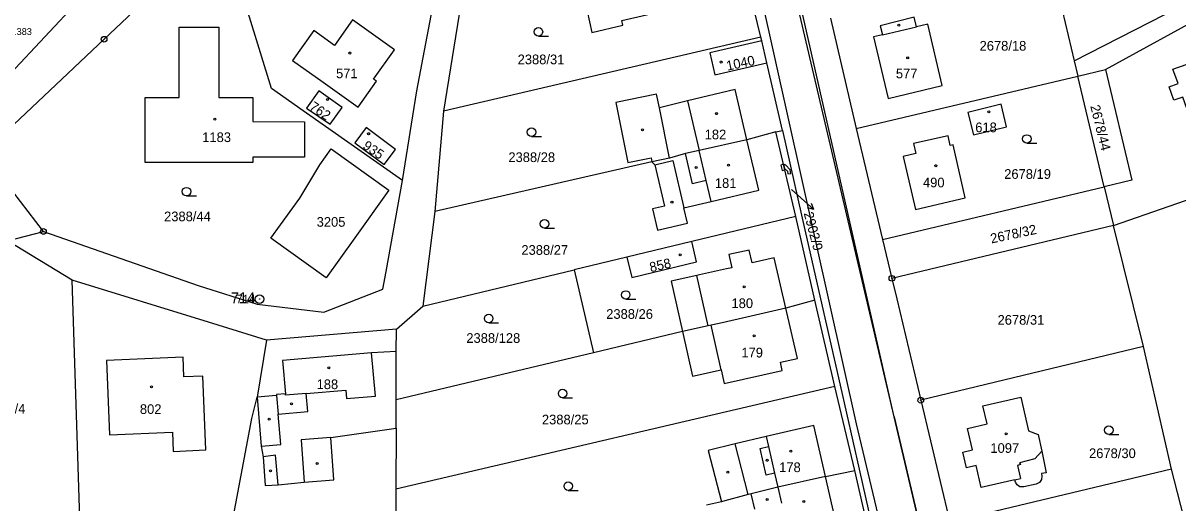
# Model space of a CAD drawing. Extents: x -758836 to -757729, y -1175316 to -1174366.
# Drawn here: x -758487.7 to -758284.7, y -1175013.2 to -1174928.9 of the extents above; entities that cross this region are included whole.
import ezdxf

# ---------------------------------------------------------------- set-up
doc = ezdxf.new("R2010")
doc.units = 0
for name, color, linetype in [('Hranice parcel', 7, 'Continuous'), ('Parcelní čísla', 7, 'Continuous'), ('Pop  PČ popisy', 7, 'Continuous'), ('Vnitřní kresba', 7, 'Continuous'), ('Vrstva 61', 7, 'Continuous'), ('Věcná břemena k části', 7, 'Continuous'), ('Značky bodu BP', 7, 'Continuous'), ('Značky budov', 7, 'Continuous'), ('Značky kultur', 7, 'Continuous')]:
    doc.layers.add(name, color=color, linetype=linetype)

msp = doc.modelspace()

# ---------------------------------------------------------------- linework, layer by layer
at = {"layer": 'Hranice parcel'}
for p, q in [((-758357.99, -1174931.4), (-758362.06, -1174914.46)), ((-758306.92, -1174918.8), (-758302.92, -1174935.57)), ((-758345.78, -1174928.06), (-758341.26, -1174947.41)), ((-758357.99, -1174931.4), (-758413.76, -1174944.36)), ((-758357.84, -1174932.05), (-758357.99, -1174931.4)), ((-758356.95, -1174935.89), (-758357.84, -1174932.05)), ((-758354.19, -1174947.79), (-758356.95, -1174935.89)), ((-758302.92, -1174935.57), (-758302.28, -1174938.23)), ((-758302.28, -1174938.23), (-758297.41, -1174937.08)), ((-758341.26, -1174947.41), (-758302.28, -1174938.23)), ((-758413.76, -1174944.36), (-758415.31, -1174962.01)), ((-758355.36, -1174948.01), (-758360.44, -1174949.43)), ((-758355.36, -1174948.01), (-758354.19, -1174947.79)), ((-758351.86, -1174962.91), (-758355.36, -1174948.01)), ((-758341.26, -1174947.41), (-758336.59, -1174966.93)), ((-758484.1, -1174965.51), (-758494.7, -1174951.75)), ((-758377.14, -1174953.27), (-758415.31, -1174962.01)), ((-758336.59, -1174966.93), (-758297.64, -1174957.65)), ((-758297.64, -1174957.65), (-758296.01, -1174964.46)), ((-758415.31, -1174962.01), (-758417.43, -1174978.6)), ((-758351.86, -1174962.91), (-758370.14, -1174967.28)), ((-758348.51, -1174977.6), (-758351.86, -1174962.91)), ((-758490.43, -1174967.13), (-758484.1, -1174965.51)), ((-758296.01, -1174964.46), (-758334.97, -1174973.74)), ((-758290.72, -1174985.7), (-758296.01, -1174964.46)), ((-758479.07, -1174974.04), (-758490.43, -1174967.13)), ((-758370.14, -1174967.28), (-758381.55, -1174970.01)), ((-758336.59, -1174966.93), (-758334.97, -1174973.74)), ((-758360.06, -1174968.77), (-758363.6, -1174969.56)), ((-758381.55, -1174970.01), (-758390.82, -1174972.23)), ((-758417.43, -1174978.6), (-758390.82, -1174972.23)), ((-758390.82, -1174972.23), (-758387.4, -1174986.81)), ((-758477.28, -1175030), (-758479.07, -1174974.04)), ((-758348.51, -1174977.6), (-758353.61, -1174978.97)), ((-758345.02, -1174992.7), (-758348.51, -1174977.6)), ((-758422.04, -1174982.66), (-758417.43, -1174978.6)), ((-758422.04, -1174982.66), (-758444.91, -1174984.58)), ((-758371.77, -1174983.1), (-758387.4, -1174986.81)), ((-758444.91, -1174984.58), (-758446.54, -1174994.59)), ((-758290.72, -1174985.7), (-758329.89, -1174995.14)), ((-758285.8, -1175007.25), (-758290.72, -1174985.7)), ((-758387.4, -1174986.81), (-758422.1, -1174995.06)), ((-758345.02, -1174992.7), (-758422.18, -1175010.77)), ((-758341.49, -1175007.47), (-758345.02, -1174992.7)), ((-758422.13, -1175000.03), (-758422.1, -1174995.06)), ((-758329.89, -1174995.14), (-758324.8, -1175016.55)), ((-758422.13, -1175000.03), (-758422.18, -1175010.77)), ((-758346.66, -1175008.52), (-758341.49, -1175007.47)), ((-758338.16, -1175021.98), (-758341.49, -1175007.47)), ((-758285.8, -1175007.25), (-758324.8, -1175016.55)), ((-758280.48, -1175027.85), (-758285.8, -1175007.25)), ((-758422.18, -1175010.77), (-758422.16, -1175026.87)), ((-758364.93, -1175012.95), (-758367.53, -1175013.58))]:
    msp.add_line(p, q, dxfattribs=at)
for points in [[(-758297.14, -1175157.07), (-758301.82, -1175137.17), (-758334.58, -1174998.03), (-758360.35, -1174888.27), (-758361.81, -1174882.07)], [(-758302.92, -1174935.57), (-758286.99, -1174927.44), (-758267.9, -1174916.47), (-758249.14, -1174905.98), (-758236.24, -1174897.16), (-758223.14, -1174884.37)], [(-758420.99, -1174956.58), (-758418.47, -1174940.81), (-758410.71, -1174900.14)], [(-758544.35, -1174980.07), (-758534.26, -1174973.76), (-758489.89, -1174937.8), (-758465.75, -1174911.99), (-758459.45, -1174912.25)], [(-758456.16, -1174915.41), (-758473.44, -1174931.75), (-758494.7, -1174951.75)], [(-758386.48, -1174920.18), (-758385.14, -1174926.03), (-758388.55, -1174926.82), (-758387.71, -1174930.55), (-758382.23, -1174929.27), (-758382.42, -1174928.48), (-758374.55, -1174926.68), (-758366.2, -1174924.79), (-758368.18, -1174916.07)], [(-758297.41, -1174937.08), (-758278.62, -1174926.8), (-758276.96, -1174925.54), (-758269.21, -1174920.77)], [(-758296.01, -1174964.46), (-758247.07, -1174947.51), (-758269.21, -1174920.77)], [(-758410.64, -1174925.24), (-758410.72, -1174925.53), (-758413.76, -1174944.36)], [(-758420.99, -1174956.58), (-758438.47, -1174944.3), (-758444.03, -1174940.39), (-758448.12, -1174927.13)], [(-758422.41, -1174933.59), (-758429.78, -1174928.35), (-758432.94, -1174932.84), (-758436.6, -1174930.22), (-758440.31, -1174935.48), (-758434.92, -1174939.3), (-758428.76, -1174943.67), (-758425.55, -1174939.12), (-758426.06, -1174938.77), (-758422.41, -1174933.59)], [(-758326.1, -1174939.86), (-758328.65, -1174929.09), (-758330.65, -1174929.56), (-758331.04, -1174927.9), (-758337.01, -1174929.38), (-758336.63, -1174930.98), (-758338.22, -1174931.36), (-758335.63, -1174942.14), (-758326.1, -1174939.86)], [(-758460.27, -1174942), (-758460.27, -1174929.65), (-758453.25, -1174929.64), (-758453.27, -1174941.98), (-758447.28, -1174941.99), (-758447.29, -1174946.22), (-758438.2, -1174946.25), (-758438.23, -1174952.48), (-758447.31, -1174952.45), (-758447.31, -1174953.41), (-758466.25, -1174953.42), (-758466.22, -1174942), (-758460.27, -1174942)], [(-758271, -1174941.74), (-758282.48, -1174945.75), (-758283.82, -1174941.92), (-758285.42, -1174942.48), (-758286.25, -1174940.1), (-758284.66, -1174939.55), (-758285.55, -1174937), (-758280.36, -1174935.18), (-758281.59, -1174931.68), (-758275.27, -1174929.47), (-758272.62, -1174937.05), (-758271.01, -1174937.37), (-758269.92, -1174940.49), (-758271, -1174941.74)], [(-758357.84, -1174932.05), (-758366.97, -1174934.14), (-758366.08, -1174938), (-758356.95, -1174935.89)], [(-758297.41, -1174937.08), (-758292.77, -1174956.49), (-758297.64, -1174957.65)], [(-758297.64, -1174957.65), (-758301.99, -1174939.46), (-758302.28, -1174938.23)], [(-758431.62, -1174943.73), (-758435.72, -1174940.79), (-758437.89, -1174943.84), (-758433.72, -1174946.69), (-758431.62, -1174943.73)], [(-758360.44, -1174949.43), (-758362.5, -1174940.61), (-758370.87, -1174942.56), (-758375.84, -1174943.78), (-758376.32, -1174941.41), (-758383.48, -1174942.85), (-758381.37, -1174953.41), (-758377.27, -1174952.58), (-758377.14, -1174953.27)], [(-758321.59, -1174944.61), (-758320.62, -1174948.55), (-758314.79, -1174947.11), (-758315.76, -1174943.17), (-758321.59, -1174944.61)], [(-758424.22, -1174953.77), (-758422.22, -1174951.09), (-758427.35, -1174947.26), (-758429.34, -1174949.94), (-758424.22, -1174953.77)], [(-758354.19, -1174947.79), (-758350.83, -1174962.63), (-758347.5, -1174977.35), (-758344.08, -1174992.47), (-758340.74, -1175007.26), (-758337.45, -1175021.81), (-758333.96, -1175036.62)], [(-758330.75, -1174951.82), (-758333.01, -1174952.34), (-758330.83, -1174961.64), (-758322.1, -1174959.62), (-758324.21, -1174950.31), (-758324.7, -1174950.42), (-758325.1, -1174948.69), (-758331.15, -1174950.07), (-758330.75, -1174951.82)], [(-758444.11, -1174966.68), (-758439.05, -1174959.65), (-758435.5, -1174953.79), (-758433.5, -1174951.03), (-758423.38, -1174958.27), (-758429.38, -1174966.65), (-758434.39, -1174973.64), (-758444.11, -1174966.68)], [(-758360.44, -1174949.43), (-758368.84, -1174951.27), (-758371.27, -1174951.84), (-758374.07, -1174952.64), (-758377.14, -1174953.27)], [(-758377.14, -1174953.27), (-758376.62, -1174953.8), (-758374.94, -1174961.04), (-758377.02, -1174961.53), (-758376.15, -1174965.26), (-758370.9, -1174964.04), (-758371.52, -1174961.37), (-758366.75, -1174960.25), (-758358.38, -1174958.26), (-758360.44, -1174949.43)], [(-758484.1, -1174965.51), (-758456.91, -1174975), (-758446.51, -1174978.25), (-758434.83, -1174979.65), (-758424.43, -1174975.65), (-758423.87, -1174972.53), (-758420.99, -1174956.58)], [(-758381.55, -1174970.01), (-758380.69, -1174973.59), (-758369.29, -1174970.86), (-758370.14, -1174967.28)], [(-758363.6, -1174969.56), (-758363.08, -1174971.87), (-758364.01, -1174972.09), (-758368.78, -1174973.13), (-758369.28, -1174973.24), (-758373.76, -1174974.24), (-758371.77, -1174983.1)], [(-758353.61, -1174978.97), (-758355.65, -1174970.15), (-758359.51, -1174971.04), (-758360.06, -1174968.77)], [(-758334.97, -1174973.74), (-758334.1, -1174977.34), (-758329.89, -1174995.14)], [(-758444.91, -1174984.58), (-758455.08, -1174981.44), (-758479.07, -1174974.04)], [(-758353.61, -1174978.97), (-758361.97, -1174980.89), (-758365.3, -1174981.64), (-758366.74, -1174981.96), (-758367.27, -1174982.08), (-758371.77, -1174983.1)], [(-758371.77, -1174983.1), (-758370.01, -1174990.93), (-758364.99, -1174989.81), (-758364.46, -1174992.19), (-758354.23, -1174989.91), (-758354.56, -1174988.45), (-758351.58, -1174987.79), (-758353.61, -1174978.97)], [(-758422.1, -1174995.06), (-758422.13, -1174986.59), (-758422.04, -1174982.66)], [(-758456.1, -1174990.92), (-758459.42, -1174991.01), (-758459.53, -1174987.58), (-758473.04, -1174988.19), (-758472.52, -1175001.23), (-758461.39, -1175000.77), (-758461.31, -1175004.15), (-758455.54, -1175003.85), (-758456.1, -1174990.92)], [(-758454.79, -1175039.02), (-758451.2, -1175018.23), (-758447.49, -1174998.37), (-758446.54, -1174994.59)], [(-758446.54, -1174994.59), (-758445.82, -1175003.19), (-758445.5, -1175005.08), (-758445.13, -1175010.09), (-758442.86, -1175009.98), (-758438.26, -1175009.5), (-758433.06, -1175009.14), (-758433.61, -1175001.68), (-758422.13, -1175000.03)], [(-758309.03, -1175009.57), (-758309.58, -1175009.85), (-758311.78, -1175010.37), (-758312.46, -1175010.32), (-758312.95, -1175010.02), (-758313.23, -1175009.55), (-758313.37, -1175009.14), (-758319.26, -1175010.49), (-758320.17, -1175006.61), (-758321.86, -1175007.01), (-758322.51, -1175004.23), (-758320.82, -1175003.84), (-758321.7, -1175000.08), (-758318.23, -1174999.29), (-758318.95, -1174996.13), (-758312.28, -1174994.61), (-758310.94, -1175000.51), (-758309.26, -1175001.14), (-758308.6, -1175004.09), (-758307.86, -1175007.86), (-758308.69, -1175008.03), (-758308.6, -1175008.49), (-758308.68, -1175009.03), (-758309.03, -1175009.57)], [(-758346.66, -1175008.52), (-758348.71, -1174999.57), (-758357.07, -1175001.48), (-758362.52, -1175002.8), (-758367.25, -1175003.97), (-758364.93, -1175012.95)], [(-758346.66, -1175008.52), (-758355.01, -1175010.43), (-758359.72, -1175011.59), (-758360.2, -1175011.71), (-758360.88, -1175011.88), (-758364.33, -1175012.8), (-758364.93, -1175012.95)], [(-758357.3, -1175026.59), (-758358.38, -1175021.51), (-758358.56, -1175020.81), (-758353, -1175019.16), (-758344.66, -1175017.24), (-758346.66, -1175008.52)]]:
    msp.add_lwpolyline(points, dxfattribs=at)
at = {"layer": 'Pop  PČ popisy'}
for p, q in [((-758352.6, -1174958.15), (-758350.94, -1174959.64)), ((-758350.94, -1174959.64), (-758348.71, -1174961.65)), ((-758348.71, -1174961.65), (-758349.79, -1174961.35)), ((-758348.71, -1174961.65), (-758349.12, -1174960.61))]:
    msp.add_line(p, q, dxfattribs=at)
at = {"layer": 'Vnitřní kresba'}
for p, q in [((-758341.2, -1174999.31), (-758361.89, -1174906.28)), ((-758334.58, -1174998.03), (-758355.8, -1174904.75)), ((-758336.63, -1174930.98), (-758330.65, -1174929.56)), ((-758370.87, -1174942.56), (-758368.84, -1174951.27)), ((-758374.07, -1174952.64), (-758375.84, -1174943.78)), ((-758367.61, -1174956.55), (-758368.84, -1174951.27)), ((-758376.62, -1174953.8), (-758373.45, -1174953.06)), ((-758373.45, -1174953.06), (-758371.52, -1174961.37)), ((-758370.04, -1174957.12), (-758371.27, -1174951.84)), ((-758367.61, -1174956.55), (-758370.04, -1174957.12)), ((-758366.75, -1174960.25), (-758367.61, -1174956.55)), ((-758367.27, -1174982.08), (-758369.28, -1174973.24)), ((-758364.99, -1174989.81), (-758366.74, -1174981.96)), ((-758426.41, -1174986.84), (-758442.07, -1174988.17)), ((-758422.13, -1174986.59), (-758426.41, -1174986.84)), ((-758425.76, -1174994.43), (-758426.41, -1174986.84)), ((-758442.07, -1174988.17), (-758441.58, -1174994.02)), ((-758441.58, -1174994.02), (-758443.16, -1174994.15)), ((-758441.56, -1174994.25), (-758441.58, -1174994.02)), ((-758437.9, -1174993.94), (-758441.56, -1174994.25)), ((-758437.9, -1174993.94), (-758430.93, -1174993.35)), ((-758437.62, -1174997.12), (-758437.9, -1174993.94)), ((-758430.93, -1174993.35), (-758430.81, -1174994.86)), ((-758443.15, -1174994.3), (-758446.54, -1174994.59)), ((-758443.16, -1174994.15), (-758443.15, -1174994.3)), ((-758443.15, -1174994.3), (-758442.85, -1174997.56)), ((-758430.81, -1174994.86), (-758425.76, -1174994.43)), ((-758442.85, -1174997.56), (-758437.62, -1174997.12)), ((-758442.39, -1175002.9), (-758442.85, -1174997.56)), ((-758334.58, -1174998.03), (-758301.51, -1175137.25)), ((-758303.3, -1175156.35), (-758341.2, -1174999.31)), ((-758433.61, -1175001.68), (-758438.79, -1175002.08)), ((-758438.79, -1175002.08), (-758438.26, -1175009.5)), ((-758357.07, -1175001.48), (-758356.66, -1175003.25)), ((-758445.82, -1175003.19), (-758442.39, -1175002.9)), ((-758360.2, -1175011.71), (-758362.52, -1175002.8)), ((-758358.12, -1175003.59), (-758356.66, -1175003.25)), ((-758357.05, -1175008.27), (-758358.12, -1175003.59)), ((-758356.66, -1175003.25), (-758355.58, -1175007.93)), ((-758309.82, -1175005.44), (-758308.6, -1175004.09)), ((-758443.34, -1175004.79), (-758445.5, -1175005.08)), ((-758442.86, -1175009.98), (-758443.34, -1175004.79)), ((-758309.82, -1175005.44), (-758312.52, -1175006.11)), ((-758312.52, -1175006.11), (-758312.38, -1175006.45)), ((-758355.58, -1175007.93), (-758357.05, -1175008.27)), ((-758355.58, -1175007.93), (-758355.01, -1175010.43)), ((-758312.38, -1175006.45), (-758312.89, -1175006.58)), ((-758312.89, -1175006.58), (-758312.35, -1175008.9)), ((-758313.37, -1175009.14), (-758312.35, -1175008.9)), ((-758359.08, -1175014.29), (-758359.72, -1175011.59)), ((-758355.01, -1175010.43), (-758354.37, -1175013.21))]:
    msp.add_line(p, q, dxfattribs=at)
at = {"layer": 'Věcná břemena k části'}
for points in [[(-758354.28, -1174954.81), (-758353.79, -1174954.69), (-758353.85, -1174954.45), (-758354.02, -1174953.72), (-758354.51, -1174953.84)], [(-758354.02, -1174953.72), (-758353.85, -1174954.45), (-758353.3, -1174954.91), (-758353.23, -1174955.39), (-758352.73, -1174955.31), (-758352.84, -1174954.67), (-758353.62, -1174953.88)]]:
    msp.add_lwpolyline(points, close=True, dxfattribs=at)
at = {"layer": 'Značky bodu BP'}
for centre, radius in [((-758473.44, -1174931.75), 0.5), ((-758473.44, -1174931.75), 0.0303), ((-758484.1, -1174965.51), 0.5), ((-758484.1, -1174965.51), 0.0303), ((-758334.97, -1174973.74), 0.5), ((-758334.97, -1174973.74), 0.0303), ((-758446.11, -1174977.38), 0.75), ((-758446.11, -1174977.38), 0.03), ((-758329.89, -1174995.14), 0.5), ((-758329.89, -1174995.14), 0.0303)]:
    msp.add_circle(centre, radius, dxfattribs=at)
at = {"layer": 'Značky budov'}
for centre in [(-758333.73, -1174929.27), (-758430.23, -1174934.18), (-758332.19, -1174935.02), (-758364.99, -1174935.76), (-758434.17, -1174942.33), (-758365.8, -1174944.82), (-758317.92, -1174944.5), (-758453.97, -1174945.78), (-758426.94, -1174948.34), (-758378.78, -1174947.66), (-758369.38, -1174954.3), (-758363.68, -1174953.87), (-758327.26, -1174953.96), (-758373.62, -1174960.38), (-758372.17, -1174969.63), (-758360.94, -1174975.23), (-758359.18, -1174983.84), (-758433.96, -1174989.47), (-758465.13, -1174992.77), (-758440.5, -1174995.79), (-758444.43, -1174998.48), (-758314.88, -1175001.02), (-758352.71, -1175004.09), (-758436, -1175006.25), (-758356.91, -1175005.69), (-758444.19, -1175007.52), (-758363.79, -1175007.79), (-758356.91, -1175012.56), (-758350.45, -1175012.94)]:
    msp.add_circle(centre, 0.175, dxfattribs=at)
at = {"layer": 'Značky kultur'}
for p, q in [((-758397.1, -1174931.22), (-758395.35, -1174931.22)), ((-758398.32, -1174948.84), (-758396.57, -1174948.84)), ((-758311.26, -1174950.02), (-758309.51, -1174950.02)), ((-758458.95, -1174959.27), (-758457.2, -1174959.27)), ((-758396.03, -1174964.93), (-758394.28, -1174964.93)), ((-758381.75, -1174977.41), (-758380, -1174977.41)), ((-758405.84, -1174981.54), (-758404.09, -1174981.54)), ((-758392.84, -1174994.7), (-758391.09, -1174994.7)), ((-758296.84, -1175001.15), (-758295.09, -1175001.15)), ((-758391.85, -1175010.98), (-758390.1, -1175010.98))]:
    msp.add_line(p, q, dxfattribs=at)
for centre in [(-758397.1, -1174930.47), (-758398.32, -1174948.09), (-758311.26, -1174949.27), (-758458.95, -1174958.52), (-758396.03, -1174964.18), (-758381.75, -1174976.66), (-758405.84, -1174980.79), (-758392.84, -1174993.95), (-758296.84, -1175000.4), (-758391.85, -1175010.23)]:
    msp.add_circle(centre, 0.75, dxfattribs=at)

# ---------------------------------------------------------------- texts
at = {"layer": 'Parcelní čísla'}
for s, p in [('2678/18', (-758319.55, -1174933.76)), ('2388/31', (-758400.75, -1174936.15)), ('571', (-758432.67, -1174938.6)), ('577', (-758334.26, -1174938.62)), ('618', (-758320.31, -1174948.08)), ('1183', (-758456.19, -1174949.81)), ('182', (-758367.87, -1174949.33)), ('2388/28', (-758402.38, -1174953.32)), ('2678/19', (-758315.22, -1174956.27)), ('181', (-758366.08, -1174957.86)), ('490', (-758329.5, -1174957.76)), ('2388/44', (-758462.9, -1174963.72)), ('3205', (-758436.08, -1174964.68)), ('2388/27', (-758400.09, -1174969.61)), ('180', (-758363.16, -1174978.96)), ('2388/26', (-758385.18, -1174980.85)), ('2678/31', (-758316.39, -1174981.88)), ('2388/128', (-758409.77, -1174985.07)), ('179', (-758361.42, -1174987.63)), ('188', (-758436.09, -1174993.19)), ('2388/4', (-758494.22, -1174997.48)), ('802', (-758467.15, -1174997.55)), ('2388/25', (-758396.48, -1174999.38)), ('1097', (-758317.65, -1175004.38)), ('2678/30', (-758300.31, -1175005.3)), ('178', (-758354.78, -1175007.76))]:
    msp.add_text(s, height=1.7, dxfattribs=at).set_placement(p)
for s, rotation, p in [('1040', 12, (-758363.88, -1174937.29)), ('762', 326, (-758437.5, -1174943.97)), ('2678/44', 284, (-758300.11, -1174943.5)), ('935', 326, (-758428.13, -1174950.83)), ('2902/9', 285, (-758350.48, -1174962.32)), ('2678/32', 12, (-758317.45, -1174967.62)), ('858', 13, (-758377.35, -1174972.67))]:
    msp.add_text(s, height=1.7, rotation=rotation, dxfattribs=at).set_placement(p)
at = {"layer": 'Vrstva 61'}
msp.add_text('475.383', height=1.2, dxfattribs=at).set_placement((-758491.94, -1174931.01))
at = {"layer": 'Značky bodu BP'}
for height, p in [(1.919, (-758451.17, -1174978.13)), (1.5, (-758450.21, -1174978.13))]:
    msp.add_text('714', height=height, dxfattribs=at).set_placement(p)

doc.saveas('drawing.dxf')
